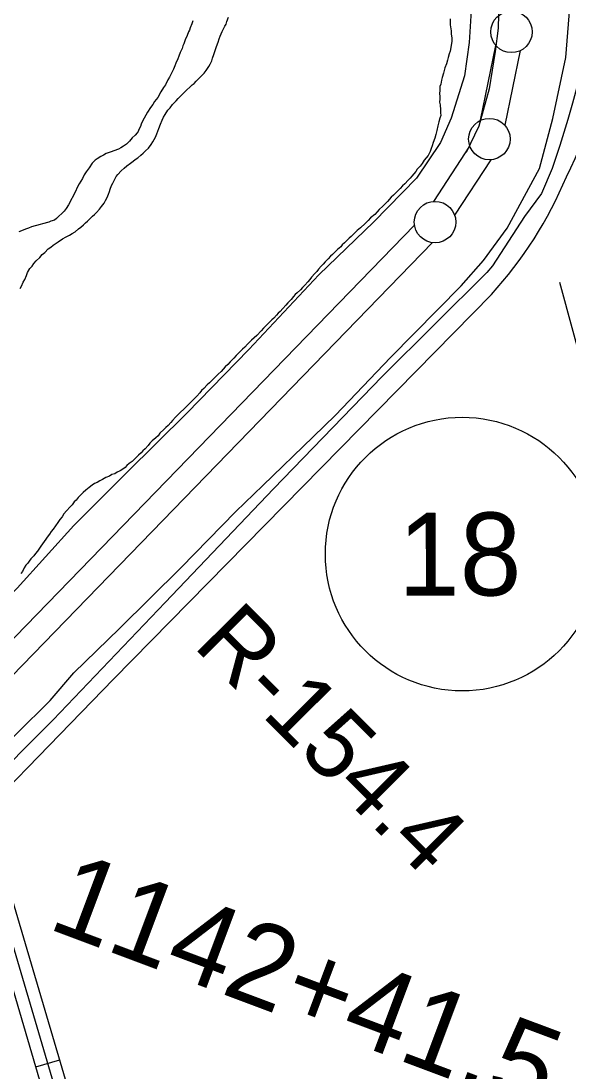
# Model space of a CAD drawing. Extents: x 3424494 to 3462436, y 522220 to 547718.
# Drawn here: x 3452364 to 3453024, y 543347 to 544612 of the extents above; entities that cross this region are included whole.
import ezdxf

# ---------------------------------------------------------------- set-up
doc = ezdxf.new("R2010")
doc.units = 0
for name, color, linetype in [('V-FLOD-BASE', 7, 'Continuous'), ('V-LEVE-TOET', 7, 'Continuous'), ('V-RIVR-EDGE', 7, 'Continuous'), ('V-RIVR-RANG-IDEN', 7, 'Continuous'), ('V-ROAD-CNTR', 7, 'Continuous'), ('V-ROAD-IDEN', 7, 'Continuous'), ('V-SITE-VEGE', 7, 'Continuous'), ('V-SURV-IDEN', 7, 'Continuous'), ('V-SURV-LINE', 7, 'Continuous'), ('V-TOPO-SHOR', 7, 'Continuous')]:
    doc.layers.add(name, color=color, linetype=linetype)

msp = doc.modelspace()

# ---------------------------------------------------------------- linework, layer by layer
at = {"layer": 'V-FLOD-BASE'}
msp.add_lwpolyline([(3452937.9, 544845.3), (3452937.9, 544736), (3452939.4, 544637.1), (3452938.8, 544603.9), (3452935.2, 544575.7), (3452927.9, 544530.7), (3452915.2, 544485.7), (3452900, 544453.9)], dxfattribs=at)
at = {"layer": 'V-LEVE-TOET'}
for points in [[(3452895, 544891), (3452903.1, 544798.8), (3452905.1, 544711.3), (3452906.4, 544631.5), (3452903.7, 544586.5), (3452898.1, 544546.5), (3452882.2, 544495.5), (3452869, 544466.1), (3452840.1, 544423), (3452788.7, 544370.3), (3452722.5, 544306.3), (3452638.2, 544216.4), (3452563.3, 544139.5), (3452490.8, 544067.5), (3452427.3, 544004.2), (3452359, 543928.7), (3452324.1, 543893.1), (3452301.4, 543869.9), (3452283.7, 543850.6), (3452258.9, 543819.8), (3452239.7, 543798.2), (3452216.2, 543775.4)], [(3451988.7, 543375.7), (3452016.5, 543396.8), (3452091.8, 543476.4), (3452192.2, 543578.7), (3452273, 543666.4), (3452358.1, 543753.1), (3452398.8, 543793.3), (3452427.1, 543826.7), (3452482.3, 543880.1), (3452556.4, 543953.2), (3452622.6, 544021.1), (3452655.1, 544052.5), (3452715.8, 544111.2), (3452742.8, 544137.3), (3452809.1, 544206.7), (3452894.2, 544293.1), (3452920.9, 544323.8), (3452949.7, 544362.7), (3452988.6, 544434.8), (3453004.7, 544495), (3453020.2, 544568.3), (3453028.5, 544674.1)]]:
    msp.add_lwpolyline(points, dxfattribs=at)
at = {"layer": 'V-RIVR-EDGE'}
msp.add_spline([(3451748, 544260.9), (3451764.4, 544271.1), (3451791.5, 544289.6), (3451819.7, 544315.2), (3451837, 544333.4), (3451853.4, 544346.5), (3451865.5, 544357.5), (3451883.9, 544373.5), (3451891.9, 544381.9), (3451901.8, 544389.5), (3451915.4, 544400.1), (3451929.3, 544415.4), (3451940.3, 544428.2), (3451954.2, 544444.2), (3451972.9, 544464.7), (3451993.4, 544482.9), (3452012.5, 544495.6), (3452023.8, 544502.9), (3452039.2, 544516.4), (3452050.2, 544527), (3452059, 544538.3), (3452067.8, 544552.9), (3452074.8, 544560.5), (3452091.2, 544571.8), (3452115.8, 544592.6), (3452128.2, 544602.8), (3452139.6, 544615.2), (3452155, 544628.3), (3452167.4, 544638.5), (3452179.9, 544650.9), (3452198.2, 544669.2), (3452207.8, 544682.3), (3452220.6, 544695.1), (3452238.5, 544714), (3452251, 544727.5), (3452258.3, 544734.8), (3452278.1, 544758.5), (3452293.2, 544775.7), (3452312.6, 544794.6), (3452329.8, 544810.7), (3452335.3, 544823.1), (3452350, 544839.5), (3452364.7, 544859.2), (3452384.1, 544880), (3452409.4, 544913.9), (3452420.8, 544928.9), (3452427.4, 544943.5), (3452428.9, 544959.2), (3452432.2, 544966.5), (3452437.7, 544973.4), (3452456.7, 544992), (3452476.9, 545011.7), (3452493, 545024.9), (3452500.7, 545030.3), (3452509.5, 545042), (3452516.5, 545052.2), (3452530.4, 545063.1), (3452544.7, 545071.1), (3452550.5, 545081), (3452571.8, 545108.4), (3452596, 545136.1), (3452616.9, 545156.9), (3452640.7, 545180.6), (3452668.6, 545210.5), (3452708.1, 545250.6), (3452727.2, 545267), (3452748.8, 545279.4), (3452766.7, 545292.1), (3452778.5, 545308.2), (3452791.7, 545319.1), (3452841.5, 545350.8), (3452868.2, 545377), (3452890.6, 545399.3), (3452902.6, 545409.1), (3452913.3, 545420.1), (3452931.6, 545429.9), (3452944.8, 545441.2), (3452999.7, 545489.3), (3453027.2, 545515.6), (3453069, 545555.7), (3453103.4, 545592.5), (3453125.8, 545625.7), (3453154.4, 545652.3), (3453181.9, 545679.7), (3453207.5, 545702.3), (3453239.4, 545730.7), (3453267.7, 545752.5)], degree=3, dxfattribs=at)
at = {"layer": 'V-ROAD-CNTR'}
msp.add_line((3452409.9, 543359.6), (3452381.1, 543351.1), dxfattribs=at)
for points in [[(3453012.8, 544297.5), (3453165.8, 543735.1), (3453267.7, 543378.2), (3453416, 542818.1)], [(3452930.5, 544282.8), (3452475, 543818.9), (3452254.7, 543592.1), (3452081.7, 543415.7)], [(3452299.9, 543638.6), (3452327, 543588.4), (3452414.7, 543290.3), (3452515.1, 542946.9), (3452627.9, 542556.6), (3452737.8, 542176.6), (3452836.6, 541842.6), (3452909.1, 541595.1), (3452941.5, 541489.7), (3453011, 541245.2), (3453069.9, 541039.1), (3453171.6, 540684.5), (3453214.2, 540548.2), (3453308.8, 540221.9), (3453394.5, 539932.3), (3453467.1, 539674.3)], [(3452313.1, 543645.7), (3452340.9, 543594.1), (3452429.1, 543294.5), (3452529.5, 542951.1), (3452642.3, 542560.8), (3452649.3, 542536.6)], [(3452286.7, 543631.5), (3452313, 543582.6), (3452400.3, 543286.1), (3452500.7, 542942.7), (3452613.5, 542552.5), (3452620.9, 542526.9)]]:
    msp.add_lwpolyline(points, dxfattribs=at)
for centre, radius, start, end in [((3452629.4, 544625.1), 439.9, 332.8686, 358.3473), ((3452572.9, 544610.4), 485, 317.5154, 337.4709)]:
    msp.add_arc(centre, radius, start, end, dxfattribs=at)
at = {"layer": 'V-ROAD-IDEN'}
msp.add_circle((3452895.4, 543969.7), 165, dxfattribs=at)
at = {"layer": 'V-SITE-VEGE'}
for points in [[(3452570.8, 544612.8), (3452569.6, 544608.9), (3452567.6, 544604.3), (3452566.7, 544601.3), (3452565.5, 544599.3), (3452563.9, 544595.1), (3452561.5, 544589.7), (3452559.9, 544585.1), (3452558.7, 544582.5), (3452557.9, 544579.4), (3452555.5, 544574.4), (3452553.8, 544570.2), (3452552.6, 544566.7), (3452550.2, 544561.7), (3452549, 544558.3), (3452547.4, 544554.4), (3452544.6, 544548.7), (3452542.6, 544544.8), (3452540.6, 544541.4), (3452537.8, 544535.6), (3452535.4, 544532.2), (3452532.2, 544527.2), (3452528.3, 544520.4), (3452524.3, 544515.4), (3452522.3, 544511.9), (3452519.6, 544508.1), (3452516, 544502.4), (3452512, 544495.5), (3452509.6, 544490.9), (3452508.4, 544488.2), (3452507.6, 544485.1), (3452505.6, 544481.7), (3452504.8, 544479.4), (3452503.6, 544477.5), (3452501.2, 544474.8), (3452497.7, 544471.4), (3452494.5, 544467.6), (3452490.6, 544463.8), (3452487.1, 544461.5), (3452484, 544459.6), (3452481.2, 544458.1), (3452471.1, 544454.4), (3452466.4, 544452.6), (3452462.9, 544450.7), (3452459.8, 544449.2), (3452455.5, 544446.2), (3452452.8, 544444.7), (3452449.2, 544440.9), (3452445.7, 544435.6), (3452442.1, 544430.6), (3452439.7, 544426.8), (3452437.7, 544422.5), (3452433.7, 544416), (3452431.4, 544411.8), (3452429.3, 544406.8)], [(3452429.3, 544406.8), (3452420.9, 544390.7), (3452418.2, 544386.5), (3452415.4, 544383.1), (3452406.4, 544374.4), (3452404, 544372.5), (3452399.7, 544371), (3452397, 544369.9), (3452389.6, 544368.1), (3452386.5, 544367), (3452376.4, 544364.1), (3452372.5, 544362.6), (3452369, 544361.5), (3452364, 544359.6), (3452360.9, 544358.1)]]:
    msp.add_lwpolyline(points, dxfattribs=at)
at = {"layer": 'V-SURV-LINE'}
for points in [[(3452917.5, 544492.8), (3452936, 544582.8)], [(3452917.5, 544492.8), (3452936, 544582.8)], [(3452965.4, 544576.7), (3452946.9, 544486.7)], [(3452965.4, 544576.7), (3452946.9, 544486.7)], [(3452861, 544395), (3452904.6, 544461.6)], [(3452861, 544395), (3452904.6, 544461.6)], [(3452929.8, 544445.2), (3452886.1, 544378.5)], [(3452929.8, 544445.2), (3452886.1, 544378.5)], [(3452122.3, 543628.9), (3452837.9, 544366.1)], [(3452122.3, 543628.9), (3452837.9, 544366.1)], [(3452859.5, 544345.3), (3452143.9, 543608)], [(3452859.5, 544345.3), (3452143.9, 543608)]]:
    msp.add_lwpolyline(points, dxfattribs=at)
for centre in [(3452954.7, 544599.3), (3452928.1, 544470.1), (3452862.6, 544370)]:
    msp.add_circle(centre, 25, dxfattribs=at)
at = {"layer": 'V-TOPO-SHOR'}
for points in [[(3453046.6, 544618.7), (3453035.7, 544540.1), (3453028.4, 544513.5), (3453022.6, 544493.7), (3453013.2, 544462.4), (3453003.8, 544434.5), (3452991, 544404.5), (3452970.6, 544376.8), (3452932, 544317.2), (3452925, 544309.1), (3452798.9, 544183.8), (3452667.9, 544048.3), (3452537.5, 543911.4), (3452402.3, 543769.9), (3452229.5, 543596.7), (3452099.2, 543461.9), (3452035.1, 543395.9), (3451996.9, 543365.7)], [(3452591.5, 544560.4), (3452593.5, 544564.6), (3452594.3, 544567.7), (3452595.9, 544571.9), (3452597.1, 544575.8), (3452599.2, 544581.9), (3452601.2, 544586.9), (3452602.4, 544590.8), (3452603.6, 544594.2), (3452606, 544599.6), (3452609.2, 544606.1), (3452610.8, 544608.8), (3452611.6, 544611.9), (3452613.7, 544617.2)], [(3452881, 544615), (3452880.9, 544610.8), (3452880.9, 544607.7), (3452881.9, 544600.7), (3452882.2, 544596.5), (3452882.9, 544592.2), (3452882.9, 544588), (3452881.6, 544580.6), (3452880.7, 544576), (3452879.5, 544573), (3452878.3, 544568.3), (3452877.5, 544565.3), (3452876.6, 544561), (3452874.6, 544556), (3452872.6, 544549.5), (3452871.3, 544544.5), (3452870.5, 544541), (3452869.6, 544536.4), (3452868.4, 544533.3), (3452868.3, 544528.7), (3452867.9, 544525.2), (3452868.2, 544521.4), (3452868.2, 544518.3), (3452868.1, 544514.4), (3452868.8, 544511.3), (3452869.1, 544505.5), (3452869, 544501.7), (3452869.4, 544498.6), (3452868.2, 544495.5), (3452867.3, 544490.9), (3452866.1, 544485.9), (3452864.8, 544480.5), (3452863.6, 544475.5), (3452862.3, 544471.2), (3452860.3, 544465.9), (3452859.1, 544462), (3452857.9, 544458.6), (3452856.7, 544455.1), (3452854.3, 544450.1), (3452849.5, 544444.8), (3452847.1, 544440.6), (3452844.8, 544437.5), (3452841.2, 544433.7), (3452839.3, 544431.1), (3452834.5, 544425.3), (3452832.6, 544423.1), (3452830.2, 544420.4), (3452826.3, 544416.2), (3452823.5, 544413.6), (3452820.4, 544410.5), (3452815.6, 544405.6), (3452812.5, 544402.5), (3452809.8, 544399.9), (3452805.4, 544394.9), (3452802.7, 544392.3), (3452799.5, 544389.2), (3452795.2, 544385.1), (3452792.8, 544382.4), (3452790.1, 544379.3), (3452785, 544375.2), (3452781.9, 544371.8), (3452778.3, 544368.3), (3452772.8, 544363), (3452768.9, 544360), (3452765.8, 544357), (3452761.4, 544352.8), (3452759.1, 544350.5), (3452753.6, 544344.8), (3452750.8, 544342.5), (3452748.9, 544340.2), (3452744.9, 544336.8), (3452739, 544331.1), (3452736.7, 544328.9), (3452733.9, 544325.8), (3452730, 544322), (3452727.6, 544319.3), (3452725.3, 544316.7), (3452722.1, 544313.3), (3452720.2, 544310.6), (3452717.8, 544307.9), (3452713.9, 544303.7), (3452711.5, 544300.7), (3452709.1, 544298), (3452705.6, 544293.8), (3452702.8, 544291.2), (3452700.5, 544288.5), (3452696.5, 544284.7), (3452694.2, 544282.8), (3452692.2, 544280.1), (3452689.1, 544276.7), (3452685.1, 544272.5), (3452682.8, 544269.9), (3452679.2, 544265.7), (3452676.1, 544262.3), (3452673.7, 544260.4), (3452671.7, 544257.7), (3452668.2, 544254.3), (3452665.8, 544252)], [(3452362.4, 544290), (3452364, 544292.6), (3452366, 544297.6), (3452368, 544300.7), (3452370, 544305.7), (3452371.6, 544309.1), (3452374.4, 544314.1), (3452377.2, 544316.8), (3452379.1, 544320.2), (3452381.9, 544323.2), (3452386.2, 544327.4), (3452389, 544330.8), (3452392.1, 544333.5), (3452396.4, 544337.7), (3452399.6, 544339.9), (3452402.3, 544342.2), (3452405.8, 544344.5), (3452408.2, 544346.4), (3452413.6, 544349.8), (3452417.9, 544352.4), (3452422.2, 544354.2), (3452425.3, 544356.1), (3452428.9, 544358.4), (3452432.8, 544361.8), (3452435.5, 544363.7), (3452439, 544366.7), (3452441.4, 544369), (3452443.8, 544371.3), (3452446.1, 544373.5), (3452449.7, 544377), (3452452, 544379.2), (3452454.4, 544381.5), (3452458.3, 544385.7), (3452460.7, 544388.8), (3452463.8, 544393), (3452465.4, 544396), (3452467.4, 544399.5), (3452469, 544403.7), (3452470.2, 544406.8), (3452471.1, 544409.8), (3452472.7, 544414.1), (3452474.3, 544417.1), (3452475.9, 544420.2), (3452478.3, 544424.8), (3452480.3, 544427.4), (3452484.2, 544432), (3452488.1, 544435), (3452491.2, 544437.7), (3452495.6, 544441.1), (3452498.7, 544443.4), (3452501, 544445.3), (3452504.5, 544447.5), (3452508.1, 544450.6), (3452510.8, 544453.2), (3452513.6, 544455.9), (3452517.1, 544459.3), (3452520.3, 544463.5), (3452522.6, 544466.9), (3452524.2, 544469.6), (3452525.8, 544472.3), (3452527.4, 544476.5), (3452529.5, 544483), (3452531.9, 544488), (3452533.9, 544493), (3452535.5, 544496.5), (3452537.5, 544499.9), (3452540.7, 544504.9), (3452543.4, 544507.9), (3452546.2, 544511.7), (3452550.5, 544516.3), (3452552.9, 544519), (3452555.6, 544521.6), (3452558.8, 544524.7), (3452561.5, 544527.3), (3452563.5, 544529.6), (3452567, 544532.6), (3452569.8, 544535.3), (3452572.1, 544537.2), (3452574.5, 544539.8), (3452577.6, 544542.9), (3452580.8, 544545.9), (3452584.3, 544549.7), (3452586.7, 544552.8), (3452589.9, 544557.4), (3452591.5, 544560.4)], [(3452665.8, 544252), (3452663.5, 544249.7), (3452660, 544246.3), (3452656, 544242.1), (3452652.9, 544239.1), (3452647.8, 544233.4), (3452644.6, 544230.3), (3452641.5, 544227.7), (3452636.4, 544222.7), (3452633.2, 544219.3), (3452630.5, 544216.7), (3452625.8, 544212.1), (3452623, 544209.1), (3452619.9, 544206), (3452615.5, 544201.5), (3452612.8, 544198.4), (3452609.6, 544195.4), (3452604.9, 544190), (3452601.4, 544186.6), (3452597.9, 544183.6), (3452593.5, 544179), (3452590.8, 544176.4), (3452588, 544173.7), (3452584.1, 544169.5), (3452581.3, 544166.9), (3452579, 544164.2), (3452575.4, 544160), (3452572.7, 544157.4), (3452569.9, 544154.7), (3452566, 544150.5), (3452562.9, 544147.5), (3452560.1, 544144.8), (3452555.4, 544140.3), (3452552.3, 544137.2), (3452549.9, 544134.9), (3452546.3, 544130.8), (3452544, 544128.5), (3452540.8, 544124.7), (3452538.1, 544122.4), (3452535.7, 544120.1), (3452531, 544115.6), (3452528.7, 544112.5), (3452525.9, 544109.9), (3452521.6, 544106.1), (3452518.8, 544103.4), (3452516.9, 544100.7), (3452513.3, 544096.5), (3452510.6, 544094.3), (3452508.6, 544092), (3452505.1, 544089), (3452502.7, 544086.7), (3452497.6, 544081.4), (3452494.1, 544079.1), (3452491.3, 544076.4), (3452489, 544074.2), (3452486.2, 544072.3), (3452483.1, 544070), (3452479.6, 544068.5), (3452476.5, 544066.6), (3452473, 544065.5), (3452470.3, 544063.7), (3452466, 544062.2), (3452461.7, 544059.5), (3452458.6, 544058.1), (3452455.5, 544056.2), (3452452.3, 544054.7), (3452449.2, 544052.8), (3452445.7, 544050.2), (3452441.8, 544046.7), (3452438.6, 544044.1), (3452434.7, 544040.3), (3452432.4, 544038), (3452430, 544034.6), (3452427.6, 544032.7), (3452425.2, 544029.3), (3452422.9, 544026.6), (3452418.6, 544022), (3452415, 544018.2), (3452413, 544014.8), (3452410.3, 544011.3), (3452407.9, 544007.9), (3452405.1, 544003.7), (3452402.3, 543999.9), (3452400, 543996.8), (3452398, 543993.8), (3452395.2, 543990), (3452393.3, 543987.7), (3452389.3, 543981.9), (3452387.3, 543979.3), (3452383.3, 543973.2), (3452381, 543970.5), (3452379, 543967.8), (3452375.5, 543964), (3452373.5, 543961.3), (3452371.9, 543958.7), (3452369.5, 543956.4), (3452367.2, 543953.3), (3452365.2, 543948.7), (3452363.2, 543946.5)]]:
    msp.add_lwpolyline(points, dxfattribs=at)

# ---------------------------------------------------------------- texts
at = {"layer": 'V-RIVR-RANG-IDEN'}
msp.add_text('R-154.4', height=83, rotation=314.9493, dxfattribs=at).set_placement((3452569.7, 543858.6))
at = {"layer": 'V-ROAD-IDEN'}
msp.add_text('18', height=100, rotation=0.2226, dxfattribs=at).set_placement((3452818.1, 543919.4))
at = {"layer": 'V-SURV-IDEN'}
msp.add_text('1142+41.5', height=100, rotation=339.4517, dxfattribs=at).set_placement((3452393.8, 543519))

doc.saveas('drawing.dxf')
